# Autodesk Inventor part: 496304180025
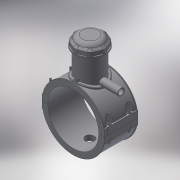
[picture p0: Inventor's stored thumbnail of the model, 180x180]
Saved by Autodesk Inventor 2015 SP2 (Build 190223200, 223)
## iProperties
Created: 2017-07
Part Number: 496304180025
Material: Generic
Description: PLASSON TAPPING SADDLE 180x25
Document SubType Name: Modeling
Designer: KIM
Mass: 1712.7 g
Surface Area: 2671.49 cm^2
Volume: 1712.7 cm^3
Density: 1 g/cm^3
Appearance: Default
Author: KIM
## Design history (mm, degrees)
derived "496304.ipt"
feature "Solid1::496304.ipt"
feature "Solid2::496304.ipt"
feature "Solid4::496304.ipt"
feature "Solid5::496304.ipt"
tag "TaggingFeature1"
body "Solid1"
body "Solid2"
other parameters: "d2" = 219, "d3" = 45, "d4" = 118, "d5" = 0, "d6" = 0.1, "d8" = 0, "d19" = 6, "d20" = 6, "d21" = 70.8, "d23" = 0, "d24" = 35.4, "d26" = 0, "d29" = 3, "d31" = 6, "d32" = 0, "d33" = 0, "d34" = 0.6, "d40" = 112.32, "d41" = 108, "d43" = 0, "d45" = 0, "d47" = 178.8, "d70" = 15, "d72" = 0, "d73" = 6, "d75" = 5, "d76" = 0, "d77" = 9, "d79" = 15, "d80" = 47.2, "d82" = 5 deg, "d84" = 4, "d85" = 14, "d86" = 0, "d87" = 3, "d88" = 0, "d89" = 1, "d90" = 1, "d91" = 94.4, "d92" = 0, "d93" = 0.5, "d94" = 94.73684, "d96" = 220.32, "d97" = 2.36, "d98" = 0, "d102" = 1.8, "d120" = 140 deg, "d121" = 24.228, "d122" = 20 deg, "d123" = 432, "d124" = 129.6, "d126" = 0, "d143" = 185.4, "d145" = 27.69231, "d149" = 2.7, "d150" = 30.46154, "d153" = 118, "d154" = 0, "d156" = 108, "d157" = 160 deg, "d159" = 7.2, "d161" = 2.7, "d162" = 70.8, "d163" = 0, "d167" = 18, "d168" = 105.36585, "d170" = 3.375, "d172" = 0, "d173" = 1, "d176" = 20 deg, "d177" = 12.6, "d178" = 36, "d180" = 0, "d183" = 14.4, "d184" = 10.08, "d185" = 38.35, "d186" = 38.35, "d187" = 108, "d188" = 10.8, "d189" = 12.6, "d190" = 0, "d191" = 162, "d193" = 6.3, "d194" = 4.13, "d195" = 90 deg, "d197" = 0, "d199" = 0, "d200" = 18, "d202" = 0, "d203" = 138, "d204" = 102.6, "d205" = 75.6, "d206" = 91.8, "d207" = 103.5, "d208" = 107.64, "d209" = 128.34, "d210" = 92.88, "d211" = 108, "d212" = 86.4, "d213" = 4.95, "d216" = 0, "d217" = 18, "d218" = 18, "d219" = 3.6, "d224" = 0, "d230" = 7.2, "d233" = 6, "d236" = 109.5, "d237" = 35.4, "d238" = 6.02433, "d240" = 35.4, "d241" = 35.4, "d242" = 35.4, "d243" = 6, "d244" = 35.4, "d245" = 35.4, "d246" = 35.4, "d247" = 6, "d248" = 6, "d249" = 6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
